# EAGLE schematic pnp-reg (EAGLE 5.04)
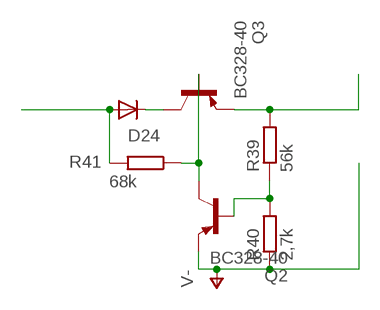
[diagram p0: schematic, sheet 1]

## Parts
D24  Z20  DIODE-D-7.5  [D-7.5]
Q2  BC328-40  [TO92-EBC]
Q3  BC328-40  [TO92-EBC]
R39  56k  R-EU_0207/10  [0207/10]
R40  2,7k  R-EU_0204/2V  [0204V]
R41  68k  R-EU_0207/10  [0207/10]

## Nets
N$1: D24.C Q3.C
N$38: Q2.C Q3.B R41.1
N$41: Q2.B R39.1 R40.2
V-: Q2.E R40.1
VCC: Q3.E R39.2
VIN: D24.A R41.2

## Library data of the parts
D24 = diode-1:DIODE-: DIODE
Q2 Q3 = transistor-pnp:BC328*: PNP Transistror
R39-R41 = rcl-2:R-EU_: RESISTOR, European symbol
